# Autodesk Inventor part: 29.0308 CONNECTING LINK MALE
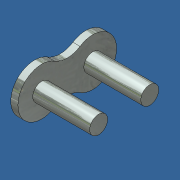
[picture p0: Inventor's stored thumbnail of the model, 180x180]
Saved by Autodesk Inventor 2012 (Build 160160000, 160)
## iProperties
Created: 2013-10
Part Number: 29.0308 CONNECTING LINK MALE
Material: Steel
Document SubType Name: Modeling
Designer: Admin
Density: 7.85 g/cm^3
Description: CONNECTING LINK 08B MALE
Mass: 7.00612 g
Surface Area: 10.1116 cm^2
Volume: 0.892499 cm^3
Author: Admin
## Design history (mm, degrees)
node "Product1"
node "Base1"
body "Solid1"
